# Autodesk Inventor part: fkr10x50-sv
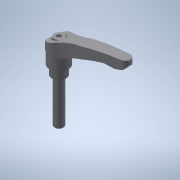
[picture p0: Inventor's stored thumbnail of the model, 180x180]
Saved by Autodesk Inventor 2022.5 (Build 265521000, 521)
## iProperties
Created: 2017-09
Part Number: fkr10x50-sv
Material: 一般
Document SubType Name: Modeling
Designer: imaocorp
Density: 1 g/cm^3
Appearance: 既定
Author: imaocorp
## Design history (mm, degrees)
node "fkr10x50-sv.x_t1"
node "fkr10x50-sv"
node "Base1"
